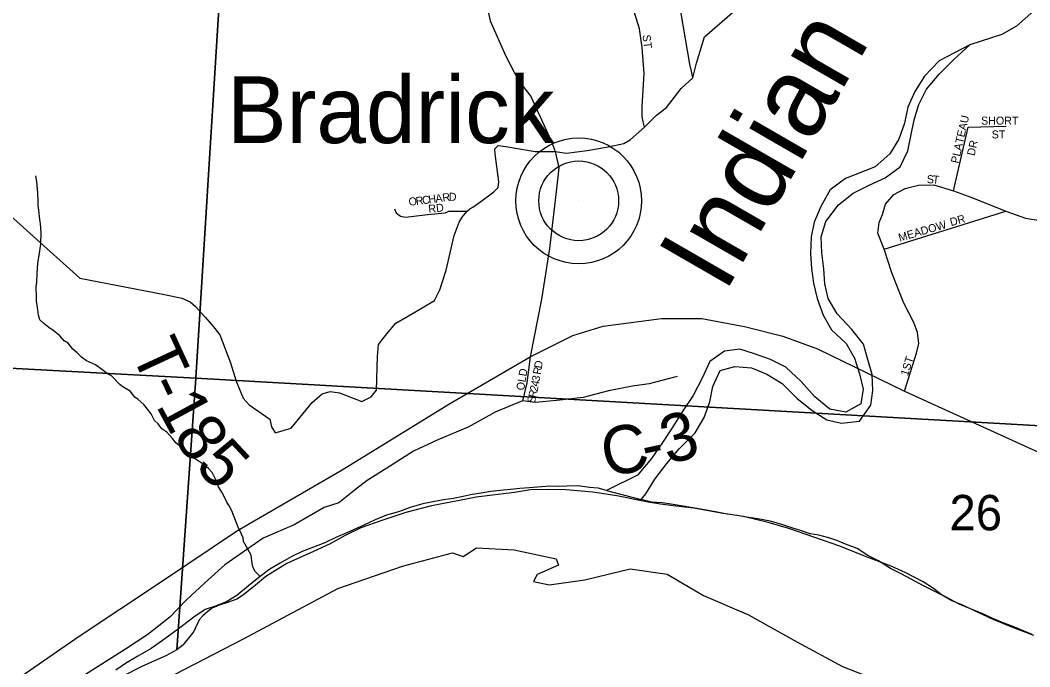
# Model space of a CAD drawing. Extents: x 0 to 34, y 0 to 22.
# Drawn here: x 6.583 to 7.778, y 16.581 to 17.345 of the extents above; entities that cross this region are included whole.
import ezdxf

# ---------------------------------------------------------------- set-up
doc = ezdxf.new("R2010")
doc.units = 0
for name, color, linetype in [('GM_X_County', 7, 'Continuous'), ('GM_X_County_Road', 7, 'Continuous'), ('GM_X_County_Road_Text', 7, 'Continuous'), ('GM_X_County_Subdivision', 7, 'Continuous'), ('GM_X_County_Subdivision_Text', 7, 'Continuous'), ('GM_X_Major_River', 7, 'Continuous'), ('GM_X_Major_River_Text', 7, 'Continuous'), ('GM_X_Minor_River', 7, 'Continuous'), ('GM_X_Section', 7, 'Continuous'), ('GM_X_Section_Text', 7, 'Continuous'), ('GM_X_State_Route', 7, 'Continuous'), ('GM_X_Township', 7, 'Continuous'), ('GM_X_Township_Road', 7, 'Continuous'), ('GM_X_Township_Road_Text', 7, 'Continuous'), ('GM_X_Township_ROW', 7, 'Continuous'), ('GM_X_Township_Subdivision', 7, 'Continuous'), ('GM_X_Township_Subdivision_Text', 7, 'Continuous'), ('GM_X_Unincorporated', 7, 'Continuous'), ('GM_X_Unincorporated_Location', 7, 'Continuous'), ('GM_X_Unincorporated_Text', 7, 'Continuous')]:
    doc.layers.add(name, color=color, linetype=linetype)

msp = doc.modelspace()

# ---------------------------------------------------------------- linework, layer by layer
at = {"layer": 'GM_X_County'}
msp.add_lwpolyline([(6.7425, 16.5601), (6.8471, 16.6139), (6.9585, 16.6734), (7.0351, 16.6998), (7.0943, 16.7158), (7.1068, 16.7113), (7.1227, 16.7216), (7.1671, 16.719), (7.2172, 16.7085), (7.2199, 16.7012), (7.1945, 16.6898), (7.1903, 16.6818), (7.2089, 16.6777), (7.251, 16.6838), (7.3045, 16.6965), (7.3485, 16.6905), (7.3915, 16.6651), (7.4446, 16.6424), (7.502, 16.6105), (7.5559, 16.5814), (7.6303, 16.5522)], dxfattribs=at)
at = {"layer": 'GM_X_County_Road'}
msp.add_lwpolyline([(7.3602, 16.924), (7.3269, 16.9153), (7.3072, 16.9126), (7.2791, 16.907), (7.2489, 16.8994), (7.2179, 16.8958), (7.192, 16.8932), (7.1772, 16.8955), (7.145, 16.8821), (7.1128, 16.8642), (7.0771, 16.8494), (7.048, 16.836), (7.0199, 16.8178), (6.9934, 16.801), (6.9794, 16.7904), (6.9677, 16.7809), (6.9597, 16.7748), (6.9423, 16.7691), (6.9067, 16.7489), (6.8703, 16.7329), (6.8248, 16.7014), (6.8009, 16.6797), (6.779, 16.6595), (6.7597, 16.6394), (6.7335, 16.6192), (6.7074, 16.6017), (6.6555, 16.569)], dxfattribs=at)
at = {"layer": 'GM_X_County_Subdivision'}
msp.add_lwpolyline([(7.1864, 16.9474), (7.1824, 16.9168), (7.1772, 16.8955)], dxfattribs=at)
at = {"layer": 'GM_X_Major_River'}
msp.add_line((7.2767, 16.7892), (7.3176, 16.7787), dxfattribs=at)
for points in [[(7.7067, 17.3163), (7.6703, 17.2973), (7.6529, 17.2791), (7.6415, 17.2609), (7.6332, 17.2427), (7.6294, 17.2237), (7.6225, 17.2047), (7.6119, 17.1872), (7.5945, 17.172), (7.5596, 17.1584), (7.5415, 17.1447), (7.5301, 17.125), (7.5225, 17.1067), (7.5187, 17.0893), (7.5179, 17.0695), (7.5194, 17.052), (7.5216, 17.0345), (7.5261, 17.0163), (7.5329, 16.9965), (7.5427, 16.9791), (7.5601, 16.9631), (7.57, 16.9456), (7.576, 16.9274), (7.5805, 16.9091), (7.5775, 16.8916), (7.56, 16.8818), (7.5411, 16.8856), (7.523, 16.9), (7.5071, 16.9183), (7.4889, 16.935), (7.4708, 16.9441), (7.4519, 16.951), (7.4345, 16.9563), (7.4163, 16.9541), (7.3989, 16.9419), (7.3898, 16.9222), (7.3791, 16.9016), (7.367, 16.8834), (7.3549, 16.8644), (7.3427, 16.8462), (7.3298, 16.8272), (7.3132, 16.8074), (7.2767, 16.7892)], [(7.3176, 16.7787), (7.323, 16.7854), (7.3336, 16.8029), (7.348, 16.8211), (7.3624, 16.8386), (7.3814, 16.8576), (7.392, 16.8758), (7.3988, 16.894), (7.4026, 16.9123), (7.411, 16.9313), (7.4284, 16.9358), (7.4481, 16.9343), (7.4662, 16.9267), (7.4844, 16.916), (7.5018, 16.8985), (7.5199, 16.8841), (7.5373, 16.8727), (7.5547, 16.8689), (7.5759, 16.8711), (7.5896, 16.8901), (7.5919, 16.9076), (7.5911, 16.9266), (7.5859, 16.9441), (7.5806, 16.9623), (7.567, 16.9798), (7.5496, 16.9981), (7.539, 17.0163), (7.5352, 17.0338), (7.5338, 17.0513), (7.5315, 17.0703), (7.5308, 17.0893), (7.5361, 17.1075), (7.5513, 17.1272), (7.5687, 17.1409), (7.5884, 17.1508), (7.6066, 17.1591), (7.624, 17.172), (7.6331, 17.191), (7.6407, 17.2275), (7.6461, 17.2457), (7.6552, 17.2639), (7.6703, 17.2814), (7.6878, 17.2988), (7.7067, 17.3163)], [(7.2767, 16.7892), (7.2669, 16.7922), (7.2566, 16.793), (7.2426, 16.7948), (7.2298, 16.7944), (7.2195, 16.794), (7.2097, 16.7944), (7.1851, 16.7924), (7.1741, 16.7916), (7.1628, 16.7904), (7.1507, 16.7892), (7.1393, 16.7881), (7.1283, 16.7861), (7.1174, 16.7846), (7.1068, 16.7823), (7.0954, 16.78), (7.0837, 16.7784), (7.0712, 16.7761), (7.0591, 16.7734), (7.0455, 16.7696), (7.0304, 16.7642), (7.016, 16.76), (7.0028, 16.7546), (6.9895, 16.7485), (6.9691, 16.7394), (6.9563, 16.7336), (6.943, 16.7275), (6.9298, 16.7225), (6.9162, 16.7172), (6.9033, 16.7107), (6.8905, 16.7034), (6.878, 16.6962), (6.8667, 16.6878), (6.8554, 16.6787), (6.8391, 16.6653), (6.8267, 16.6577), (6.8127, 16.6523), (6.8017, 16.6485), (6.7881, 16.6397), (6.7749, 16.6294), (6.7609, 16.6191), (6.7481, 16.61), (6.7375, 16.6024), (6.722, 16.5936), (6.7073, 16.5848), (6.6959, 16.5768)], [(7.7803, 16.6189), (7.7708, 16.6231), (7.7587, 16.628), (7.7462, 16.6329), (7.734, 16.6381), (7.7211, 16.6438), (7.7075, 16.6495), (7.6942, 16.6551), (7.6787, 16.6631), (7.6643, 16.6703), (7.6525, 16.6763), (7.6252, 16.6907), (7.6127, 16.6971), (7.5987, 16.7062), (7.5858, 16.7126), (7.5733, 16.7209), (7.5596, 16.7258), (7.5494, 16.73), (7.5399, 16.7334), (7.5278, 16.7364), (7.5176, 16.7382), (7.5074, 16.7416), (7.496, 16.745), (7.4831, 16.7495), (7.4702, 16.7529), (7.4558, 16.7559), (7.4422, 16.7578), (7.4312, 16.7596), (7.4195, 16.7615), (7.4055, 16.7641), (7.3903, 16.7667), (7.3786, 16.769), (7.365, 16.7712), (7.3532, 16.7731), (7.3426, 16.7746), (7.3297, 16.7757), (7.3176, 16.7787)]]:
    msp.add_lwpolyline(points, dxfattribs=at)
at = {"layer": 'GM_X_Minor_River'}
for points in [[(7.7825, 17.3565), (7.762, 17.3383), (7.7446, 17.3284), (7.7067, 17.3163)], [(6.8667, 16.6878), (6.8609, 16.6936), (6.8583, 16.6979), (6.8573, 16.7028), (6.856, 16.7127), (6.8501, 16.7235), (6.8471, 16.7292), (6.8465, 16.7334), (6.8446, 16.7377), (6.8406, 16.7461), (6.8377, 16.753), (6.833, 16.7652), (6.8301, 16.771), (6.8271, 16.7756), (6.822, 16.786), (6.8172, 16.7937), (6.815, 16.8005), (6.8099, 16.8105), (6.8055, 16.8155), (6.8002, 16.8198), (6.7909, 16.826), (6.7815, 16.8315), (6.7763, 16.8381), (6.7673, 16.8451), (6.7629, 16.8509), (6.7562, 16.8582), (6.7502, 16.8621), (6.7461, 16.8683), (6.7417, 16.8721), (6.7376, 16.8798), (6.7291, 16.891), (6.7224, 16.8968), (6.7183, 16.8995), (6.7127, 16.9069), (6.7052, 16.9112), (6.7011, 16.9143), (6.6907, 16.9247), (6.6858, 16.9271), (6.6791, 16.9325), (6.6716, 16.938), (6.6611, 16.9427), (6.6551, 16.947), (6.6499, 16.952), (6.645, 16.9563), (6.6395, 16.9636), (6.6346, 16.9664), (6.6294, 16.9722), (6.6227, 16.9776), (6.6167, 16.9819), (6.6107, 16.9869), (6.6059, 16.9912), (6.6041, 16.9965), (6.6034, 17.003), (6.6027, 17.0084), (6.6021, 17.0129), (6.6021, 17.0171), (6.6016, 17.0301), (6.6025, 17.0357), (6.6026, 17.046), (6.6031, 17.0525), (6.604, 17.0608), (6.6049, 17.0673), (6.6062, 17.0756), (6.607, 17.0805), (6.6073, 17.0942), (6.6067, 17.1045), (6.606, 17.1098), (6.6047, 17.1209), (6.604, 17.1262), (6.6037, 17.1315), (6.6035, 17.1414), (6.6032, 17.1456), (6.6023, 17.1548), (6.6012, 17.1613)]]:
    msp.add_lwpolyline(points, dxfattribs=at)
at = {"layer": 'GM_X_Section'}
for points in [[(5.784, 17.9889), (6.8533, 17.9287), (6.7904, 16.9223), (5.726, 16.9791)], [(6.8533, 17.9287), (7.9078, 17.8715), (7.8396, 16.8632), (6.7904, 16.9223)]]:
    msp.add_lwpolyline(points, close=True, dxfattribs=at)
for points in [[(5.726, 16.9791), (6.7904, 16.9223), (6.7682, 16.601), (6.755, 16.5938), (6.7273, 16.5816), (6.68, 16.5577)], [(7.7822, 16.618), (7.7594, 16.6267), (7.7344, 16.6369), (7.6973, 16.654), (7.6855, 16.6589), (7.673, 16.6661), (7.6635, 16.6733), (7.6514, 16.6812), (7.6309, 16.6918), (7.6135, 16.6998), (7.5832, 16.7111), (7.5528, 16.7236), (7.4922, 16.7444), (7.468, 16.7516), (7.4388, 16.7587), (7.4122, 16.7625), (7.38, 16.7685), (7.3588, 16.7708), (7.3406, 16.7731), (7.3258, 16.7757), (7.2887, 16.7832), (7.2603, 16.7874), (7.2285, 16.79), (7.2069, 16.7904), (7.1868, 16.79), (7.1678, 16.7869), (7.1224, 16.7816), (7.1027, 16.7774), (7.0693, 16.771), (7.039, 16.7634), (7.0106, 16.7539), (6.986, 16.7451), (6.9671, 16.736), (6.9496, 16.7262), (6.9299, 16.7171), (6.9148, 16.7106), (6.8981, 16.703), (6.8735, 16.6875), (6.861, 16.6772), (6.847, 16.6658), (6.839, 16.6609), (6.8281, 16.6567), (6.8182, 16.6537), (6.8099, 16.6503), (6.805, 16.6465), (6.7989, 16.6412), (6.7944, 16.6362), (6.7883, 16.6226), (6.775, 16.6063), (6.7682, 16.601), (6.7904, 16.9223), (7.8396, 16.8632)]]:
    msp.add_lwpolyline(points, dxfattribs=at)
at = {"layer": 'GM_X_State_Route'}
for points in [[(7.0841, 17.4479), (7.0851, 17.4469), (7.1048, 17.4232), (7.1321, 17.3755), (7.139, 17.3446), (7.1574, 17.3029), (7.1726, 17.2742), (7.187, 17.2552), (7.211, 17.2029), (7.2123, 17.1996)], [(7.2123, 17.1996), (7.2158, 17.1902), (7.2203, 17.1707), (7.2179, 17.1496), (7.2091, 17.0753), (7.1995, 17.0155), (7.1864, 16.9474)], [(7.1864, 16.9474), (7.2045, 16.9563), (7.2367, 16.9724), (7.2728, 16.9836), (7.3418, 16.9926), (7.3896, 16.9926), (7.4398, 16.9834), (7.4853, 16.9717), (7.5264, 16.9569), (7.6294, 16.9068), (7.8363, 16.8124), (7.8617, 16.8021), (7.9545, 16.7583), (8.0376, 16.7228), (8.0899, 16.7064), (8.1147, 16.7016)], [(6.1519, 16.3886), (6.1796, 16.3989), (6.2278, 16.4168), (6.3229, 16.4476), (6.4385, 16.4897), (6.5509, 16.5474), (6.6523, 16.6172), (6.7498, 16.6817), (6.8399, 16.7419), (6.9637, 16.8138), (7.0899, 16.8914), (7.1864, 16.9474)]]:
    msp.add_lwpolyline(points, dxfattribs=at)
at = {"layer": 'GM_X_Township'}
msp.add_lwpolyline([(6.7425, 16.5601), (6.8471, 16.6139), (6.9585, 16.6734), (7.0351, 16.6998), (7.0943, 16.7158), (7.1068, 16.7113), (7.1227, 16.7216), (7.1671, 16.719), (7.2172, 16.7085), (7.2199, 16.7012), (7.1945, 16.6898), (7.1903, 16.6818), (7.2089, 16.6777), (7.251, 16.6838), (7.3045, 16.6965), (7.3485, 16.6905), (7.3915, 16.6651), (7.4446, 16.6424), (7.502, 16.6105), (7.5559, 16.5814), (7.6303, 16.5522)], dxfattribs=at)
at = {"layer": 'GM_X_Township_Road'}
msp.add_lwpolyline([(6.8013, 16.9946), (6.81, 16.985), (6.8191, 16.9735), (6.8317, 16.9402), (6.8381, 16.9186), (6.8467, 16.8986), (6.8537, 16.8907), (6.8781, 16.8736), (6.88, 16.8644), (6.8846, 16.8576), (6.9035, 16.8629), (6.9282, 16.8934), (6.9399, 16.9036), (6.9497, 16.9063), (6.9604, 16.9048), (6.9869, 16.8945), (6.9979, 16.8999), (7.0043, 16.9078), (7.0054, 16.9477), (7.0069, 16.962), (7.0165, 16.9745), (7.0271, 16.987), (7.0497, 17.0001), (7.0731, 17.0138), (7.0794, 17.0267), (7.087, 17.05), (7.0962, 17.0909), (7.1023, 17.1064), (7.1059, 17.1125), (7.1117, 17.1195), (7.1148, 17.1225), (7.1184, 17.1245), (7.1278, 17.1309), (7.1431, 17.1423), (7.1482, 17.1474), (7.1492, 17.1543), (7.145, 17.1873), (7.1446, 17.1935), (7.1485, 17.1972), (7.1574, 17.1959), (7.1923, 17.1902), (7.2158, 17.1902)], dxfattribs=at)
at = {"layer": 'GM_X_Township_ROW'}
msp.add_lwpolyline([(6.2021, 17.56), (6.2277, 17.5343), (6.2285, 17.5283), (6.2265, 17.5123), (6.2397, 17.4866), (6.2541, 17.4629), (6.2857, 17.4295), (6.3226, 17.3954), (6.3755, 17.3551), (6.387, 17.3469), (6.4282, 17.3342), (6.4559, 17.3076), (6.4555, 17.2802), (6.4547, 17.2513), (6.4574, 17.2342), (6.4715, 17.2166), (6.5351, 17.146), (6.6531, 17.0404), (6.7536, 17.0209), (6.7741, 17.0166), (6.7839, 17.0124), (6.7902, 17.0069), (6.8013, 16.9946)], dxfattribs=at)
at = {"layer": 'GM_X_Township_Subdivision'}
for points in [[(7.2158, 17.1902), (7.2293, 17.1883), (7.2538, 17.1914), (7.2786, 17.1956), (7.297, 17.1997), (7.3046, 17.2038), (7.3217, 17.219), (7.3357, 17.233), (7.3477, 17.2422), (7.3649, 17.2645), (7.3788, 17.2771), (7.3833, 17.2945), (7.3925, 17.3257), (7.4286, 17.3567), (7.4604, 17.3766), (7.4666, 17.3801), (7.4905, 17.3926), (7.5066, 17.3958)], [(7.3217, 17.219), (7.3201, 17.2252), (7.3186, 17.2314), (7.3189, 17.2432), (7.3211, 17.2825), (7.3189, 17.3133), (7.3157, 17.3351), (7.3049, 17.37), (7.2841, 17.3981)], [(7.3788, 17.2771), (7.3771, 17.2853), (7.3753, 17.2936), (7.362, 17.3697)], [(7.7046, 17.2189), (7.7497, 17.2201)], [(7.6874, 17.1438), (7.7046, 17.2189)], [(7.6294, 16.9068), (7.6434, 16.9515), (7.6461, 16.9633), (7.6446, 16.9762), (7.6404, 16.9879), (7.6287, 17.011), (7.6142, 17.0467), (7.6051, 17.0747), (7.5979, 17.0937), (7.5995, 17.1062), (7.6032, 17.1157), (7.607, 17.1278), (7.6165, 17.1392), (7.6302, 17.1464), (7.6457, 17.1502), (7.6639, 17.1506), (7.6874, 17.1438), (7.709, 17.1358), (7.7492, 17.1195), (7.7724, 17.1115), (7.8004, 17.107), (7.8251, 17.1051), (7.8425, 17.1081)], [(7.0258, 17.1225), (7.0276, 17.1176), (7.0328, 17.1136), (7.0387, 17.1127), (7.0487, 17.1136), (7.0646, 17.1158), (7.0859, 17.1177), (7.0899, 17.1196), (7.1117, 17.1195)], [(7.6051, 17.0747), (7.7492, 17.1195)]]:
    msp.add_lwpolyline(points, dxfattribs=at)
at = {"layer": 'GM_X_Unincorporated'}
for radius in [0.0744, 0.0472]:
    msp.add_circle((7.2437, 17.1318), radius, dxfattribs=at)
at = {"layer": 'GM_X_Unincorporated_Location'}
msp.add_line((7.2437, 17.1318), (7.2437, 17.1318), dxfattribs=at)

# ---------------------------------------------------------------- texts
at = {"layer": 'GM_X_County_Road_Text'}
for s, rotation, p in [('3', 15.0895, (7.349, 16.8198)), ('C', 11.0721, (7.2762, 16.8048)), ('-', 12.3705, (7.3234, 16.8141))]:
    msp.add_text(s, height=0.0568, rotation=rotation, dxfattribs=at).set_placement(p)
at = {"layer": 'GM_X_County_Subdivision_Text'}
for s, rotation, p in [('OLD', 80.8365, (7.179, 16.9071)), ('R', 80.1262, (7.1987, 16.9258)), ('D', 80.2815, (7.2, 16.9332)), ('3', 79.3443, (7.1972, 16.9175)), ('2', 78.1123, (7.1948, 16.9058)), ('4', 78.6961, (7.196, 16.9117)), ('S', 77.0215, (7.1916, 16.8918)), ('R', 77.3409, (7.1931, 16.8984))]:
    msp.add_text(s, height=0.00947, rotation=rotation, dxfattribs=at).set_placement(p)
at = {"layer": 'GM_X_Major_River_Text'}
msp.add_text('Indian', height=0.09477, rotation=60.0414, dxfattribs=at).set_placement((7.4165, 17.0213))
at = {"layer": 'GM_X_Section_Text'}
msp.add_text('26', height=0.04186, rotation=0, dxfattribs=at).set_placement((7.6825, 16.7422))
at = {"layer": 'GM_X_Township_Road_Text'}
for s, rotation, p in [('T', 294.8289, (6.7129, 16.953)), ('-', 295.6085, (6.7311, 16.9136)), ('1', 298.3944, (6.7426, 16.8899)), ('8', 304.2045, (6.7625, 16.8538)), ('5', 312.9995, (6.7881, 16.8174))]:
    msp.add_text(s, height=0.0568, rotation=rotation, dxfattribs=at).set_placement(p)
at = {"layer": 'GM_X_Township_Subdivision_Text'}
for s, rotation, p in [('ST', 276.7061, (7.3192, 17.3278)), ('PLATEAU', 77.2756, (7.6932, 17.1755)), ('SHORT', 0, (7.7199, 17.2219)), ('ST', 0, (7.7325, 17.2056)), ('DR', 77.4779, (7.7123, 17.1845)), ('S', 358.955, (7.6557, 17.1527)), ('T', 354.1766, (7.6622, 17.1526)), ('R', 7.2805, (7.0514, 17.1268)), ('C', 7.2244, (7.0589, 17.1277)), ('H', 7.2226, (7.0663, 17.1287)), ('A', 7.2226, (7.0746, 17.1297)), ('R', 7.7171, (7.0829, 17.1308)), ('D', 0.6858, (7.09, 17.1318)), ('O', 4.7682, (7.0427, 17.1261)), ('RD', 6.0083, (7.0662, 17.1175)), ('DR', 15.5232, (7.6845, 17.1018)), ('MEADOW', 16.1892, (7.6236, 17.0835)), ('1ST', 72.3498, (7.6333, 16.924))]:
    msp.add_text(s, height=0.00947, rotation=rotation, dxfattribs=at).set_placement(p)
at = {"layer": 'GM_X_Unincorporated_Text'}
msp.add_text('Bradrick', height=0.07898, rotation=0, dxfattribs=at).set_placement((6.8275, 17.2001))

doc.saveas('drawing.dxf')
